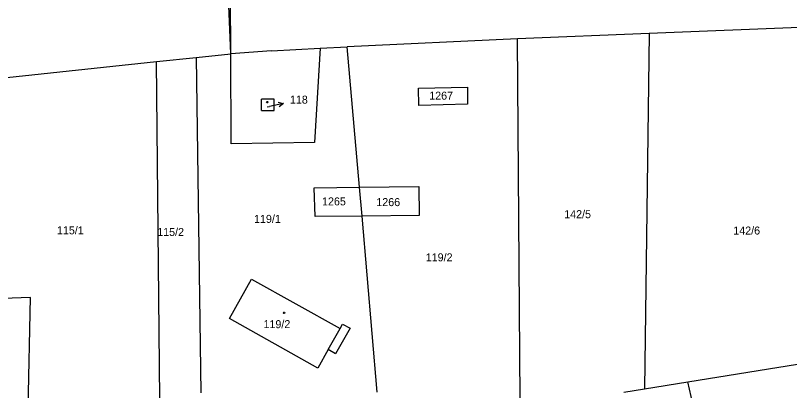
# Model space of a CAD drawing. Extents: x -812394 to -807601, y -1013097 to -1009266.
# Drawn here: x -809776.7 to -809612.2, y -1010672.5 to -1010592.7 of the extents above; entities that cross this region are included whole.
import ezdxf

# ---------------------------------------------------------------- set-up
doc = ezdxf.new("R2010")
doc.units = 0
for name, color, linetype in [('Default', 7, 'Continuous'), ('KN_HRANICE', 7, 'Continuous'), ('KN_KULTURY', 7, 'Continuous'), ('KN_PARCELY', 7, 'Continuous'), ('KN_SLUCKY', 7, 'Continuous')]:
    doc.layers.add(name, color=color, linetype=linetype)

# ---------------------------------------------------------------- blocks, each defined once
blk = doc.blocks.new('10292')
at = {"layer": 'Default'}
blk.add_line((0, 3), (0, 0), dxfattribs=at)
blk.add_lwpolyline([(-0.5, 2), (0, 3), (0.5, 2)], dxfattribs=at)
blk = doc.blocks.new('402')
at = {"layer": 'Default'}
blk.add_lwpolyline([(0.09, 0.15), (0.18, 0), (0.09, -0.15), (-0.09, -0.15), (-0.18, 0), (-0.09, 0.15), (0.09, 0.15)], dxfattribs=at)

msp = doc.modelspace()

# ---------------------------------------------------------------- linework, layer by layer
at = {"layer": 'KN_HRANICE'}
for p, q in [((-809730.9, -1010600.87), (-809735.22, -1010505.35)), ((-809730.9, -1010600.87), (-809731.22, -1010570.09)), ((-809594.54, -1010594.65), (-809642.04, -1010596.56)), ((-809642.04, -1010596.56), (-809670.02, -1010597.72)), ((-809642.04, -1010596.56), (-809643.04, -1010672.11)), ((-809670.02, -1010597.72), (-809706.23, -1010599.39)), ((-809669.42, -1010674.32), (-809670.02, -1010597.72)), ((-809722.27, -1010600.23), (-809730.9, -1010600.87)), ((-809722.27, -1010600.23), (-809711.97, -1010599.69)), ((-809711.97, -1010599.69), (-809713.11, -1010619.7)), ((-809711.97, -1010599.69), (-809706.23, -1010599.39)), ((-809703.55, -1010629.24), (-809706.23, -1010599.39)), ((-809746.74, -1010602.54), (-809738.29, -1010601.65)), ((-809738.29, -1010601.65), (-809730.9, -1010600.87)), ((-809738.29, -1010601.65), (-809737.29, -1010672.93)), ((-809730.84, -1010620.01), (-809730.9, -1010600.87)), ((-809785.03, -1010606.6), (-809746.74, -1010602.54)), ((-809745.99, -1010674.27), (-809746.74, -1010602.54)), ((-809691.02, -1010608.19), (-809680.61, -1010607.97)), ((-809690.96, -1010611.9), (-809691.02, -1010608.19)), ((-809680.61, -1010607.97), (-809680.61, -1010611.61)), ((-809680.61, -1010611.61), (-809690.96, -1010611.9)), ((-809713.11, -1010619.7), (-809730.84, -1010620.01)), ((-809713.23, -1010629.34), (-809703.55, -1010629.24)), ((-809713.01, -1010635.43), (-809713.23, -1010629.34)), ((-809703.55, -1010629.24), (-809690.96, -1010629.11)), ((-809703, -1010635.36), (-809703.55, -1010629.24)), ((-809690.96, -1010629.11), (-809690.9, -1010635.27)), ((-809703, -1010635.36), (-809713.01, -1010635.43)), ((-809690.9, -1010635.27), (-809703, -1010635.36)), ((-809699.85, -1010672.81), (-809703, -1010635.36)), ((-809731.21, -1010657.15), (-809726.56, -1010648.77)), ((-809726.56, -1010648.77), (-809707.72, -1010659.29)), ((-809773.49, -1010652.65), (-809779.36, -1010652.87)), ((-809774.04, -1010679.33), (-809773.49, -1010652.65)), ((-809712.47, -1010667.68), (-809731.21, -1010657.15)), ((-809705.6, -1010659.22), (-809708.67, -1010664.64)), ((-809707.72, -1010659.29), (-809707.18, -1010658.33)), ((-809707.18, -1010658.33), (-809705.6, -1010659.22)), ((-809710.24, -1010663.75), (-809712.47, -1010667.68)), ((-809708.67, -1010664.64), (-809710.24, -1010663.75)), ((-809633.83, -1010670.62), (-809598.46, -1010664.88)), ((-809643.04, -1010672.11), (-809633.83, -1010670.62)), ((-809632.78, -1010675.32), (-809633.83, -1010670.62)), ((-809647.44, -1010672.82), (-809643.04, -1010672.11))]:
    msp.add_line(p, q, dxfattribs=at)
at = {"layer": 'KN_PARCELY'}
msp.add_line((-809723.21, -1010612.18), (-809722.69, -1010612.07), dxfattribs=at)
at = {"layer": 'KN_SLUCKY'}
for p, q in [((-809724.37, -1010612.96), (-809724.37, -1010610.49)), ((-809721.71, -1010610.49), (-809724.37, -1010610.49)), ((-809721.71, -1010612.96), (-809721.71, -1010610.49)), ((-809724.37, -1010612.96), (-809721.71, -1010612.96)), ((-809710.24, -1010663.75), (-809707.72, -1010659.29))]:
    msp.add_line(p, q, dxfattribs=at)

# ---------------------------------------------------------------- block references
at = {"layer": 'KN_KULTURY'}
for p in [(-809723.19, -1010611.14), (-809719.6, -1010655.95)]:
    msp.add_blockref('402', p, dxfattribs=at)
at = {"layer": 'KN_PARCELY', "rotation": -78.391244}
msp.add_blockref('10292', (-809722.69, -1010612.07), dxfattribs=at)

# ---------------------------------------------------------------- texts
at = {"layer": 'KN_PARCELY'}
for s, height, p in [('118', 1.7, (-809718.36, -1010611.47)), ('1267', 1.7, (-809688.77, -1010610.62)), ('118', 0.1, (-809723.36, -1010612.18)), ('1265', 1.7, (-809711.54, -1010633.1)), ('1266', 1.7, (-809700.01, -1010633.25)), ('119/1', 1.7, (-809725.99, -1010636.82)), ('142/5', 1.7, (-809660.09, -1010635.82)), ('115/1', 1.7, (-809767.86, -1010639.25)), ('115/2', 1.7, (-809746.56, -1010639.61)), ('142/6', 1.7, (-809624.17, -1010639.3)), ('119/2', 1.7, (-809689.51, -1010644.99)), ('119/2', 1.7, (-809723.98, -1010659.2))]:
    msp.add_text(s, height=height, dxfattribs=at).set_placement(p)

doc.saveas('drawing.dxf')
